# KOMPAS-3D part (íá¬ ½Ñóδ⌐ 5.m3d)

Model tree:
1. Эскиз:1
2. Операция выдавливания:1
     Расстояние 1 = 10
3. Эскиз:2
4. Вырезать элемент выдавливания:1
     Расстояние 1 = 34.8
5. Скругление:1
     Радиус = 1
6. Скругление:2
     Радиус = 2
7. Эскиз:3
8. Операция выдавливания:2
     Расстояние 1 = 2; Расстояние 2 = 4.9
9. Скругление:3
     Радиус = 1
10. Эскиз:4
11. Вырезать элемент выдавливания:2
     Расстояние 1 = 0.2
12. Скругление:4
     Радиус = 0.1
13. Эскиз:5
14. Операция выдавливания:3
     Расстояние 1 = 0.1; Расстояние 2 = 4.9

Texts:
  бак левый 5
  Сплав АЛ8  ГОСТ 1583-93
